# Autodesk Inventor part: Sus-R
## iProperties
Created: 2007-12
Part Number: Sus-R
Document SubType Name: Modeling
Designer: UJA2299
Density: 1 g/cm^3
Author: UJA2299
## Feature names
1. 押し出し1 [Extrusion]
2. 押し出し2 [Extrusion]
3. 押し出し3 [Extrusion]
4. 面取り1 [Chamfer]
5. 押し出し4 [Extrusion]
6. 押し出し5 [Extrusion]
7. 面取り2 [Chamfer]
8. フィレット1 [Fillet]
9. フィレット2 [Fillet]
10. フィレット3 [Fillet]
